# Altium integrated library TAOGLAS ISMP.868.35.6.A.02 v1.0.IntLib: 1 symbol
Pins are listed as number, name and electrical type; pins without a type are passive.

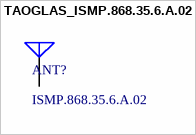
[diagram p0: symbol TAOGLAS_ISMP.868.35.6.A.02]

## TAOGLAS_ISMP.868.35.6.A.02
designator ANT?, comment ISMP.868.35.6.A.02
Embedded 2dBi 868MHz Ceramic Patch Antenna (35*35*6mm); ComponentLibStatus: Created; MFG: Taoglas; Temp_High: +85C; Temp_Low: -40C
footprint TAOGLAS_ISMP.868.35.6.A.02 (Embedded 2dBi 868MHz Ceramic Patch Antenna (35*35*6mm))
pins: 1 RF FEED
